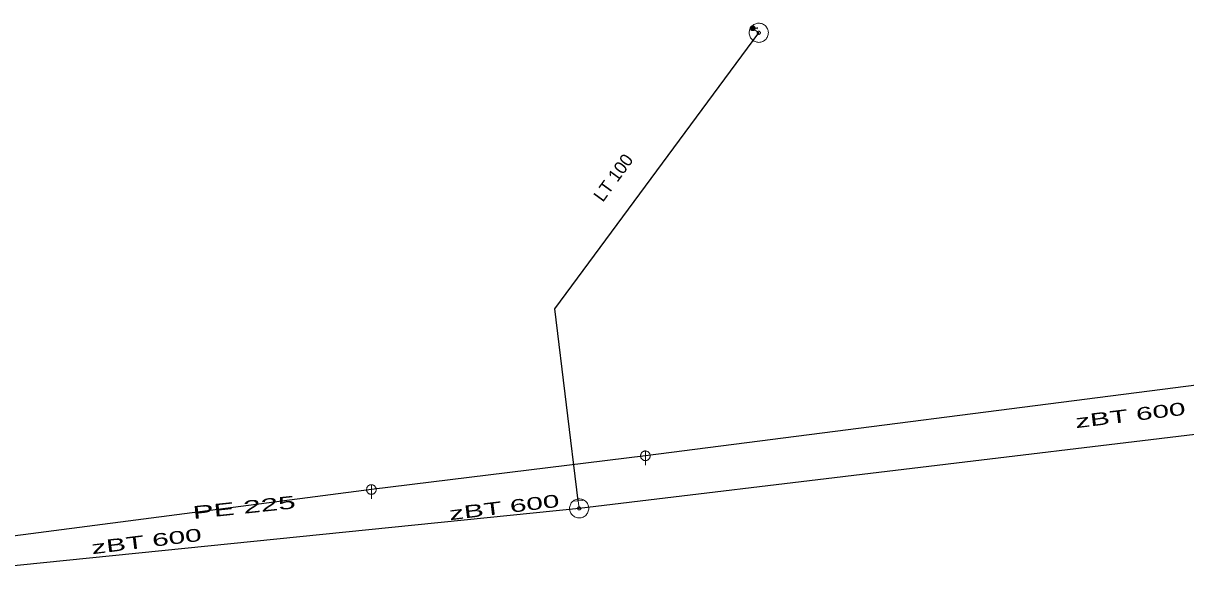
# Model space of a CAD drawing. Extents: x -687515 to -686506, y -974029 to -973461.
# Drawn here: x -686751.9 to -686691.1, y -973640.8 to -973611.7 of the extents above; entities that cross this region are included whole.
import ezdxf
from ezdxf.enums import TextEntityAlignment as Align

# ---------------------------------------------------------------- set-up
doc = ezdxf.new("R2010")
doc.units = 0
doc.header["$LTSCALE"] = 0.27
for name, color, linetype, lineweight in [('1', 7, 'Continuous', 13), ('14', 7, 'Continuous', 25), ('17', 7, 'Continuous', 25), ('22', 7, 'Continuous', 13), ('34', 7, 'Continuous', 13), ('47', 7, 'Continuous', 13), ('9', 7, 'Continuous', 13)]:
    doc.layers.add(name, color=color, linetype=linetype, lineweight=lineweight)

msp = doc.modelspace()

# ---------------------------------------------------------------- linework, layer by layer
at = {"layer": '14', "lineweight": 13}
for p, q in [((-686713.734, -973611.941), (-686713.412, -973612.179)), ((-686722.863, -973636.678), (-686722.815, -973637.075))]:
    msp.add_line(p, q, dxfattribs=at)
at = {"layer": '14'}
for p, q in [((-686667.587, -973627.675), (-686719.348, -973634.32)), ((-686719.348, -973634.32), (-686733.692, -973636.086)), ((-686733.692, -973636.086), (-686757.083, -973639.12))]:
    msp.add_line(p, q, dxfattribs=at)
at = {"layer": '17'}
for p, q in [((-686623.461, -973625.138), (-686722.815, -973637.075)), ((-686722.815, -973637.075), (-686759.568, -973640.809))]:
    msp.add_line(p, q, dxfattribs=at)
msp.add_lwpolyline([(-686722.863, -973636.678), (-686724.094, -973626.633), (-686713.412, -973612.179)], dxfattribs=at)
at = {"layer": '22'}
for p, q in [((-686719.347, -973634.068), (-686719.348, -973634.811)), ((-686733.691, -973635.834), (-686733.692, -973636.578))]:
    msp.add_line(p, q, dxfattribs=at)
for points in [[(-686719.096, -973634.32), (-686719.097, -973634.294), (-686719.101, -973634.268), (-686719.107, -973634.242), (-686719.117, -973634.218), (-686719.129, -973634.194), (-686719.143, -973634.172), (-686719.16, -973634.151), (-686719.178, -973634.133), (-686719.199, -973634.116), (-686719.221, -973634.102), (-686719.245, -973634.09), (-686719.269, -973634.08), (-686719.295, -973634.074), (-686719.321, -973634.07), (-686719.347, -973634.068), (-686719.373, -973634.069), (-686719.399, -973634.073), (-686719.425, -973634.079), (-686719.45, -973634.089), (-686719.473, -973634.101), (-686719.495, -973634.115), (-686719.516, -973634.132), (-686719.534, -973634.15), (-686719.551, -973634.171), (-686719.565, -973634.193), (-686719.577, -973634.217), (-686719.587, -973634.241), (-686719.594, -973634.267), (-686719.598, -973634.293), (-686719.6, -973634.319), (-686719.599, -973634.345), (-686719.595, -973634.371), (-686719.588, -973634.397), (-686719.578, -973634.422), (-686719.566, -973634.445), (-686719.552, -973634.467), (-686719.535, -973634.488), (-686719.517, -973634.506), (-686719.496, -973634.523), (-686719.474, -973634.537), (-686719.451, -973634.549), (-686719.426, -973634.559), (-686719.4, -973634.566), (-686719.374, -973634.57), (-686719.348, -973634.571), (-686719.322, -973634.571), (-686719.296, -973634.567), (-686719.27, -973634.56), (-686719.246, -973634.55), (-686719.222, -973634.538), (-686719.2, -973634.524), (-686719.179, -973634.507), (-686719.161, -973634.489), (-686719.144, -973634.468), (-686719.13, -973634.446), (-686719.118, -973634.423), (-686719.108, -973634.398), (-686719.102, -973634.372), (-686719.098, -973634.346)], [(-686733.44, -973636.086), (-686733.441, -973636.06), (-686733.445, -973636.034), (-686733.451, -973636.008), (-686733.461, -973635.984), (-686733.473, -973635.96), (-686733.487, -973635.938), (-686733.504, -973635.917), (-686733.522, -973635.899), (-686733.543, -973635.882), (-686733.565, -973635.868), (-686733.589, -973635.856), (-686733.613, -973635.846), (-686733.639, -973635.84), (-686733.665, -973635.836), (-686733.691, -973635.834), (-686733.717, -973635.835), (-686733.743, -973635.839), (-686733.769, -973635.845), (-686733.794, -973635.855), (-686733.817, -973635.867), (-686733.839, -973635.881), (-686733.86, -973635.898), (-686733.878, -973635.916), (-686733.895, -973635.937), (-686733.909, -973635.959), (-686733.921, -973635.983), (-686733.931, -973636.007), (-686733.938, -973636.033), (-686733.942, -973636.059), (-686733.944, -973636.085), (-686733.943, -973636.111), (-686733.939, -973636.137), (-686733.932, -973636.163), (-686733.922, -973636.188), (-686733.91, -973636.211), (-686733.896, -973636.233), (-686733.879, -973636.254), (-686733.861, -973636.272), (-686733.84, -973636.289), (-686733.818, -973636.303), (-686733.795, -973636.315), (-686733.77, -973636.325), (-686733.744, -973636.332), (-686733.718, -973636.336), (-686733.692, -973636.338), (-686733.666, -973636.337), (-686733.64, -973636.333), (-686733.614, -973636.326), (-686733.59, -973636.316), (-686733.566, -973636.304), (-686733.544, -973636.29), (-686733.523, -973636.273), (-686733.505, -973636.255), (-686733.488, -973636.234), (-686733.474, -973636.212), (-686733.462, -973636.189), (-686733.452, -973636.164), (-686733.446, -973636.138), (-686733.442, -973636.112)]]:
    msp.add_lwpolyline(points, close=True, dxfattribs=at)
at = {"layer": '34'}
msp.add_line((-686723.11, -973636.699), (-686722.615, -973636.656), dxfattribs=at)
at = {"layer": '47'}
for points in [[(-686712.915, -973612.117), (-686712.925, -973612.066), (-686712.939, -973612.015), (-686712.959, -973611.967), (-686712.983, -973611.921), (-686713.013, -973611.877), (-686713.047, -973611.837), (-686713.085, -973611.801), (-686713.126, -973611.769), (-686713.17, -973611.741), (-686713.217, -973611.718), (-686713.266, -973611.7), (-686713.317, -973611.688), (-686713.369, -973611.68), (-686713.421, -973611.679), (-686713.473, -973611.682), (-686713.524, -973611.692), (-686713.575, -973611.706), (-686713.624, -973611.726), (-686713.669, -973611.75), (-686713.713, -973611.78), (-686713.753, -973611.814), (-686713.79, -973611.852), (-686713.822, -973611.893), (-686713.85, -973611.937), (-686713.872, -973611.984), (-686713.89, -973612.033), (-686713.903, -973612.084), (-686713.91, -973612.136), (-686713.911, -973612.188), (-686713.908, -973612.24), (-686713.898, -973612.291), (-686713.884, -973612.342), (-686713.865, -973612.391), (-686713.84, -973612.436), (-686713.81, -973612.48), (-686713.777, -973612.52), (-686713.739, -973612.557), (-686713.698, -973612.589), (-686713.653, -973612.617), (-686713.606, -973612.639), (-686713.557, -973612.657), (-686713.507, -973612.67), (-686713.454, -973612.677), (-686713.402, -973612.678), (-686713.35, -973612.675), (-686713.299, -973612.665), (-686713.248, -973612.651), (-686713.2, -973612.632), (-686713.154, -973612.607), (-686713.11, -973612.577), (-686713.07, -973612.544), (-686713.034, -973612.506), (-686713.002, -973612.465), (-686712.974, -973612.42), (-686712.951, -973612.373), (-686712.933, -973612.324), (-686712.921, -973612.274), (-686712.913, -973612.221), (-686712.912, -973612.169)], [(-686713.33, -973612.168), (-686713.331, -973612.159), (-686713.334, -973612.152), (-686713.337, -973612.144), (-686713.341, -973612.137), (-686713.346, -973612.129), (-686713.352, -973612.123), (-686713.358, -973612.116), (-686713.364, -973612.111), (-686713.372, -973612.107), (-686713.38, -973612.103), (-686713.388, -973612.1), (-686713.396, -973612.098), (-686713.404, -973612.097), (-686713.413, -973612.096), (-686713.422, -973612.097), (-686713.431, -973612.098), (-686713.438, -973612.101), (-686713.446, -973612.104), (-686713.453, -973612.108), (-686713.461, -973612.113), (-686713.467, -973612.119), (-686713.474, -973612.125), (-686713.479, -973612.131), (-686713.484, -973612.139), (-686713.487, -973612.147), (-686713.49, -973612.155), (-686713.492, -973612.163), (-686713.493, -973612.171), (-686713.494, -973612.18), (-686713.493, -973612.189), (-686713.492, -973612.198), (-686713.489, -973612.205), (-686713.486, -973612.213), (-686713.482, -973612.22), (-686713.477, -973612.228), (-686713.472, -973612.234), (-686713.465, -973612.241), (-686713.459, -973612.246), (-686713.451, -973612.251), (-686713.443, -973612.254), (-686713.435, -973612.257), (-686713.427, -973612.259), (-686713.419, -973612.26), (-686713.41, -973612.261), (-686713.401, -973612.26), (-686713.392, -973612.259), (-686713.385, -973612.256), (-686713.377, -973612.253), (-686713.37, -973612.249), (-686713.362, -973612.244), (-686713.356, -973612.239), (-686713.349, -973612.232), (-686713.344, -973612.226), (-686713.34, -973612.218), (-686713.336, -973612.21), (-686713.333, -973612.202), (-686713.331, -973612.194), (-686713.33, -973612.186), (-686713.329, -973612.177)], [(-686722.318, -973637.013), (-686722.328, -973636.962), (-686722.342, -973636.911), (-686722.362, -973636.863), (-686722.386, -973636.817), (-686722.416, -973636.773), (-686722.45, -973636.733), (-686722.488, -973636.697), (-686722.529, -973636.665), (-686722.573, -973636.637), (-686722.62, -973636.614), (-686722.669, -973636.596), (-686722.72, -973636.584), (-686722.772, -973636.576), (-686722.824, -973636.575), (-686722.876, -973636.578), (-686722.927, -973636.588), (-686722.978, -973636.602), (-686723.027, -973636.622), (-686723.072, -973636.646), (-686723.116, -973636.676), (-686723.156, -973636.71), (-686723.193, -973636.748), (-686723.225, -973636.789), (-686723.253, -973636.833), (-686723.275, -973636.88), (-686723.293, -973636.929), (-686723.306, -973636.98), (-686723.313, -973637.032), (-686723.314, -973637.084), (-686723.311, -973637.136), (-686723.301, -973637.187), (-686723.287, -973637.238), (-686723.268, -973637.287), (-686723.243, -973637.332), (-686723.213, -973637.376), (-686723.18, -973637.416), (-686723.142, -973637.453), (-686723.101, -973637.485), (-686723.056, -973637.513), (-686723.009, -973637.535), (-686722.96, -973637.553), (-686722.91, -973637.566), (-686722.857, -973637.573), (-686722.805, -973637.574), (-686722.753, -973637.571), (-686722.702, -973637.561), (-686722.651, -973637.547), (-686722.603, -973637.528), (-686722.557, -973637.503), (-686722.513, -973637.473), (-686722.473, -973637.44), (-686722.437, -973637.402), (-686722.405, -973637.361), (-686722.377, -973637.316), (-686722.354, -973637.269), (-686722.336, -973637.22), (-686722.324, -973637.17), (-686722.316, -973637.117), (-686722.315, -973637.065)], [(-686722.733, -973637.064), (-686722.734, -973637.055), (-686722.737, -973637.048), (-686722.74, -973637.04), (-686722.744, -973637.033), (-686722.749, -973637.025), (-686722.755, -973637.019), (-686722.761, -973637.012), (-686722.767, -973637.007), (-686722.775, -973637.003), (-686722.783, -973636.999), (-686722.791, -973636.996), (-686722.799, -973636.994), (-686722.807, -973636.993), (-686722.816, -973636.992), (-686722.825, -973636.993), (-686722.834, -973636.994), (-686722.841, -973636.997), (-686722.849, -973637), (-686722.856, -973637.004), (-686722.864, -973637.009), (-686722.87, -973637.015), (-686722.877, -973637.021), (-686722.882, -973637.027), (-686722.887, -973637.035), (-686722.89, -973637.043), (-686722.893, -973637.051), (-686722.895, -973637.059), (-686722.896, -973637.067), (-686722.897, -973637.076), (-686722.896, -973637.085), (-686722.895, -973637.094), (-686722.892, -973637.101), (-686722.889, -973637.109), (-686722.885, -973637.116), (-686722.88, -973637.124), (-686722.875, -973637.13), (-686722.868, -973637.137), (-686722.862, -973637.142), (-686722.854, -973637.147), (-686722.846, -973637.15), (-686722.838, -973637.153), (-686722.83, -973637.155), (-686722.822, -973637.156), (-686722.813, -973637.157), (-686722.804, -973637.156), (-686722.795, -973637.155), (-686722.788, -973637.152), (-686722.78, -973637.149), (-686722.773, -973637.145), (-686722.765, -973637.14), (-686722.759, -973637.135), (-686722.752, -973637.128), (-686722.747, -973637.122), (-686722.743, -973637.114), (-686722.739, -973637.106), (-686722.736, -973637.098), (-686722.734, -973637.09), (-686722.733, -973637.082), (-686722.732, -973637.073)]]:
    msp.add_lwpolyline(points, close=True, dxfattribs=at)
at = {"layer": '9'}
msp.add_line((-686713.608, -973611.941), (-686713.482, -973611.941), dxfattribs=at)
for points in [[(-686713.734, -973612.067), (-686713.721, -973612.066), (-686713.708, -973612.064), (-686713.695, -973612.061), (-686713.683, -973612.056), (-686713.671, -973612.05), (-686713.66, -973612.043), (-686713.65, -973612.035), (-686713.64, -973612.025), (-686713.632, -973612.015), (-686713.625, -973612.004), (-686713.619, -973611.992), (-686713.614, -973611.98), (-686713.611, -973611.967), (-686713.609, -973611.954), (-686713.608, -973611.941), (-686713.608, -973611.928), (-686713.61, -973611.915), (-686713.613, -973611.902), (-686713.618, -973611.89), (-686713.624, -973611.878), (-686713.631, -973611.867), (-686713.639, -973611.857), (-686713.649, -973611.847), (-686713.659, -973611.839), (-686713.67, -973611.832), (-686713.682, -973611.826), (-686713.694, -973611.821), (-686713.707, -973611.818), (-686713.72, -973611.816), (-686713.733, -973611.815), (-686713.746, -973611.815), (-686713.759, -973611.817), (-686713.772, -973611.82), (-686713.784, -973611.825), (-686713.796, -973611.831), (-686713.807, -973611.838), (-686713.817, -973611.846), (-686713.827, -973611.856), (-686713.835, -973611.866), (-686713.842, -973611.877), (-686713.848, -973611.889), (-686713.853, -973611.901), (-686713.856, -973611.914), (-686713.858, -973611.927), (-686713.86, -973611.94), (-686713.859, -973611.953), (-686713.857, -973611.966), (-686713.854, -973611.979), (-686713.849, -973611.991), (-686713.843, -973612.003), (-686713.836, -973612.014), (-686713.828, -973612.024), (-686713.818, -973612.034), (-686713.808, -973612.042), (-686713.797, -973612.049), (-686713.785, -973612.055), (-686713.773, -973612.06), (-686713.76, -973612.063), (-686713.747, -973612.065)], [(-686713.734, -973612.047), (-686713.723, -973612.047), (-686713.712, -973612.045), (-686713.701, -973612.042), (-686713.691, -973612.038), (-686713.681, -973612.033), (-686713.672, -973612.027), (-686713.663, -973612.02), (-686713.655, -973612.012), (-686713.648, -973612.003), (-686713.642, -973611.994), (-686713.637, -973611.984), (-686713.633, -973611.974), (-686713.63, -973611.963), (-686713.628, -973611.952), (-686713.628, -973611.941), (-686713.627, -973611.93), (-686713.629, -973611.919), (-686713.632, -973611.908), (-686713.636, -973611.898), (-686713.641, -973611.888), (-686713.647, -973611.879), (-686713.654, -973611.87), (-686713.662, -973611.862), (-686713.671, -973611.855), (-686713.68, -973611.849), (-686713.69, -973611.844), (-686713.7, -973611.84), (-686713.711, -973611.837), (-686713.722, -973611.835), (-686713.733, -973611.835), (-686713.744, -973611.834), (-686713.755, -973611.836), (-686713.766, -973611.839), (-686713.776, -973611.843), (-686713.786, -973611.848), (-686713.795, -973611.854), (-686713.804, -973611.861), (-686713.812, -973611.869), (-686713.819, -973611.878), (-686713.825, -973611.887), (-686713.83, -973611.897), (-686713.834, -973611.907), (-686713.837, -973611.918), (-686713.839, -973611.929), (-686713.84, -973611.94), (-686713.84, -973611.951), (-686713.838, -973611.962), (-686713.835, -973611.973), (-686713.831, -973611.983), (-686713.826, -973611.993), (-686713.82, -973612.002), (-686713.813, -973612.011), (-686713.805, -973612.019), (-686713.796, -973612.026), (-686713.787, -973612.032), (-686713.777, -973612.037), (-686713.767, -973612.041), (-686713.756, -973612.044), (-686713.745, -973612.046)], [(-686713.734, -973612.028), (-686713.725, -973612.027), (-686713.716, -973612.026), (-686713.707, -973612.023), (-686713.699, -973612.02), (-686713.691, -973612.016), (-686713.683, -973612.011), (-686713.676, -973612.005), (-686713.67, -973611.999), (-686713.664, -973611.992), (-686713.659, -973611.984), (-686713.655, -973611.976), (-686713.652, -973611.968), (-686713.649, -973611.959), (-686713.648, -973611.95), (-686713.647, -973611.941), (-686713.647, -973611.932), (-686713.648, -973611.923), (-686713.651, -973611.914), (-686713.654, -973611.906), (-686713.658, -973611.898), (-686713.663, -973611.89), (-686713.669, -973611.883), (-686713.675, -973611.877), (-686713.682, -973611.871), (-686713.69, -973611.866), (-686713.698, -973611.862), (-686713.706, -973611.859), (-686713.715, -973611.856), (-686713.724, -973611.855), (-686713.733, -973611.853), (-686713.742, -973611.854), (-686713.751, -973611.855), (-686713.76, -973611.858), (-686713.768, -973611.861), (-686713.776, -973611.865), (-686713.784, -973611.87), (-686713.791, -973611.876), (-686713.797, -973611.882), (-686713.803, -973611.889), (-686713.808, -973611.897), (-686713.812, -973611.905), (-686713.815, -973611.913), (-686713.818, -973611.922), (-686713.819, -973611.931), (-686713.821, -973611.94), (-686713.82, -973611.949), (-686713.819, -973611.958), (-686713.816, -973611.967), (-686713.813, -973611.975), (-686713.809, -973611.983), (-686713.804, -973611.991), (-686713.798, -973611.998), (-686713.792, -973612.004), (-686713.785, -973612.01), (-686713.777, -973612.015), (-686713.769, -973612.019), (-686713.761, -973612.022), (-686713.752, -973612.025), (-686713.743, -973612.026)], [(-686713.734, -973612.008), (-686713.727, -973612.008), (-686713.72, -973612.006), (-686713.713, -973612.005), (-686713.707, -973612.002), (-686713.701, -973611.999), (-686713.695, -973611.995), (-686713.689, -973611.991), (-686713.684, -973611.986), (-686713.68, -973611.98), (-686713.676, -973611.974), (-686713.673, -973611.968), (-686713.67, -973611.962), (-686713.669, -973611.955), (-686713.667, -973611.948), (-686713.667, -973611.941), (-686713.666, -973611.934), (-686713.668, -973611.927), (-686713.669, -973611.92), (-686713.672, -973611.914), (-686713.675, -973611.907), (-686713.679, -973611.902), (-686713.683, -973611.896), (-686713.688, -973611.891), (-686713.694, -973611.887), (-686713.7, -973611.883), (-686713.706, -973611.88), (-686713.712, -973611.877), (-686713.719, -973611.875), (-686713.726, -973611.874), (-686713.733, -973611.874), (-686713.74, -973611.873), (-686713.747, -973611.874), (-686713.754, -973611.876), (-686713.76, -973611.879), (-686713.767, -973611.882), (-686713.772, -973611.886), (-686713.778, -973611.89), (-686713.783, -973611.895), (-686713.787, -973611.901), (-686713.791, -973611.906), (-686713.794, -973611.913), (-686713.797, -973611.919), (-686713.799, -973611.926), (-686713.8, -973611.933), (-686713.801, -973611.94), (-686713.801, -973611.947), (-686713.8, -973611.954), (-686713.798, -973611.961), (-686713.795, -973611.967), (-686713.792, -973611.973), (-686713.788, -973611.979), (-686713.784, -973611.985), (-686713.779, -973611.99), (-686713.773, -973611.994), (-686713.768, -973611.998), (-686713.761, -973612.001), (-686713.755, -973612.004), (-686713.748, -973612.005), (-686713.741, -973612.007)], [(-686713.734, -973611.988), (-686713.729, -973611.988), (-686713.724, -973611.987), (-686713.719, -973611.986), (-686713.715, -973611.984), (-686713.71, -973611.982), (-686713.706, -973611.979), (-686713.703, -973611.976), (-686713.699, -973611.972), (-686713.696, -973611.969), (-686713.693, -973611.965), (-686713.691, -973611.96), (-686713.689, -973611.956), (-686713.688, -973611.951), (-686713.687, -973611.946), (-686713.687, -973611.941), (-686713.686, -973611.936), (-686713.687, -973611.931), (-686713.688, -973611.926), (-686713.69, -973611.922), (-686713.692, -973611.917), (-686713.695, -973611.913), (-686713.698, -973611.909), (-686713.702, -973611.906), (-686713.705, -973611.903), (-686713.709, -973611.9), (-686713.714, -973611.898), (-686713.718, -973611.896), (-686713.723, -973611.895), (-686713.728, -973611.894), (-686713.733, -973611.894), (-686713.738, -973611.893), (-686713.743, -973611.894), (-686713.748, -973611.895), (-686713.752, -973611.897), (-686713.757, -973611.899), (-686713.761, -973611.902), (-686713.765, -973611.905), (-686713.768, -973611.908), (-686713.771, -973611.912), (-686713.774, -973611.916), (-686713.776, -973611.921), (-686713.778, -973611.925), (-686713.779, -973611.93), (-686713.78, -973611.935), (-686713.781, -973611.94), (-686713.781, -973611.945), (-686713.78, -973611.95), (-686713.779, -973611.955), (-686713.777, -973611.959), (-686713.775, -973611.964), (-686713.772, -973611.968), (-686713.769, -973611.971), (-686713.766, -973611.975), (-686713.762, -973611.978), (-686713.758, -973611.981), (-686713.753, -973611.983), (-686713.749, -973611.985), (-686713.744, -973611.986), (-686713.739, -973611.987)], [(-686713.734, -973611.968), (-686713.731, -973611.968), (-686713.728, -973611.968), (-686713.726, -973611.967), (-686713.723, -973611.966), (-686713.72, -973611.965), (-686713.718, -973611.963), (-686713.716, -973611.961), (-686713.714, -973611.959), (-686713.712, -973611.957), (-686713.71, -973611.955), (-686713.709, -973611.952), (-686713.708, -973611.949), (-686713.707, -973611.947), (-686713.707, -973611.944), (-686713.707, -973611.941), (-686713.706, -973611.938), (-686713.706, -973611.935), (-686713.707, -973611.932), (-686713.708, -973611.93), (-686713.709, -973611.927), (-686713.711, -973611.925), (-686713.713, -973611.922), (-686713.715, -973611.92), (-686713.717, -973611.919), (-686713.719, -973611.917), (-686713.722, -973611.916), (-686713.725, -973611.915), (-686713.727, -973611.914), (-686713.73, -973611.914), (-686713.733, -973611.913), (-686713.736, -973611.913), (-686713.739, -973611.913), (-686713.742, -973611.914), (-686713.744, -973611.915), (-686713.747, -973611.916), (-686713.749, -973611.918), (-686713.752, -973611.919), (-686713.754, -973611.921), (-686713.755, -973611.924), (-686713.757, -973611.926), (-686713.758, -973611.929), (-686713.759, -973611.931), (-686713.76, -973611.934), (-686713.761, -973611.937), (-686713.762, -973611.94), (-686713.761, -973611.943), (-686713.761, -973611.946), (-686713.76, -973611.948), (-686713.759, -973611.951), (-686713.758, -973611.954), (-686713.756, -973611.956), (-686713.755, -973611.958), (-686713.753, -973611.96), (-686713.75, -973611.962), (-686713.748, -973611.964), (-686713.745, -973611.965), (-686713.743, -973611.966), (-686713.74, -973611.967), (-686713.737, -973611.967)], [(-686713.734, -973611.949), (-686713.733, -973611.949), (-686713.732, -973611.949), (-686713.732, -973611.948), (-686713.731, -973611.948), (-686713.73, -973611.948), (-686713.729, -973611.947), (-686713.729, -973611.947), (-686713.728, -973611.946), (-686713.728, -973611.946), (-686713.727, -973611.945), (-686713.727, -973611.944), (-686713.727, -973611.943), (-686713.726, -973611.943), (-686713.726, -973611.942), (-686713.726, -973611.941), (-686713.726, -973611.94), (-686713.726, -973611.939), (-686713.727, -973611.939), (-686713.727, -973611.938), (-686713.726, -973611.937), (-686713.727, -973611.936), (-686713.727, -973611.936), (-686713.728, -973611.935), (-686713.728, -973611.935), (-686713.729, -973611.934), (-686713.73, -973611.934), (-686713.731, -973611.933), (-686713.731, -973611.933), (-686713.732, -973611.933), (-686713.733, -973611.933), (-686713.734, -973611.933), (-686713.735, -973611.933), (-686713.735, -973611.933), (-686713.736, -973611.933), (-686713.737, -973611.933), (-686713.738, -973611.934), (-686713.738, -973611.934), (-686713.739, -973611.935), (-686713.739, -973611.935), (-686713.74, -973611.936), (-686713.74, -973611.937), (-686713.742, -973611.938), (-686713.742, -973611.938), (-686713.742, -973611.939), (-686713.742, -973611.94), (-686713.742, -973611.941), (-686713.742, -973611.942), (-686713.742, -973611.942), (-686713.741, -973611.943), (-686713.741, -973611.944), (-686713.74, -973611.945), (-686713.74, -973611.945), (-686713.739, -973611.946), (-686713.739, -973611.946), (-686713.738, -973611.947), (-686713.737, -973611.947), (-686713.736, -973611.947), (-686713.736, -973611.948), (-686713.735, -973611.948)]]:
    msp.add_lwpolyline(points, close=True, dxfattribs=at)
msp.add_lwpolyline([(-686713.516, -973611.91), (-686713.482, -973611.941), (-686713.517, -973611.972)], dxfattribs=at)

# ---------------------------------------------------------------- texts
at = {"layer": '1'}
msp.add_text('LT 100', height=0.6667, rotation=54, dxfattribs=at).set_placement((-686720.758, -973619.957), align=Align.CENTER)
for s, rotation, width, p in [('zBT 600 ', 7, 1.75, (-686693.709, -973632.495)), ('PE 225', 6, 1.85, (-686740.319, -973637.348)), ('zBT 600 ', 7, 1.75, (-686726.484, -973637.315)), ('zBT 600 ', 7, 1.75, (-686745.211, -973639.095))]:
    msp.add_text(s, height=0.6667, rotation=rotation, dxfattribs=dict(at, width=width)).set_placement(p, align=Align.CENTER)

doc.saveas('drawing.dxf')
